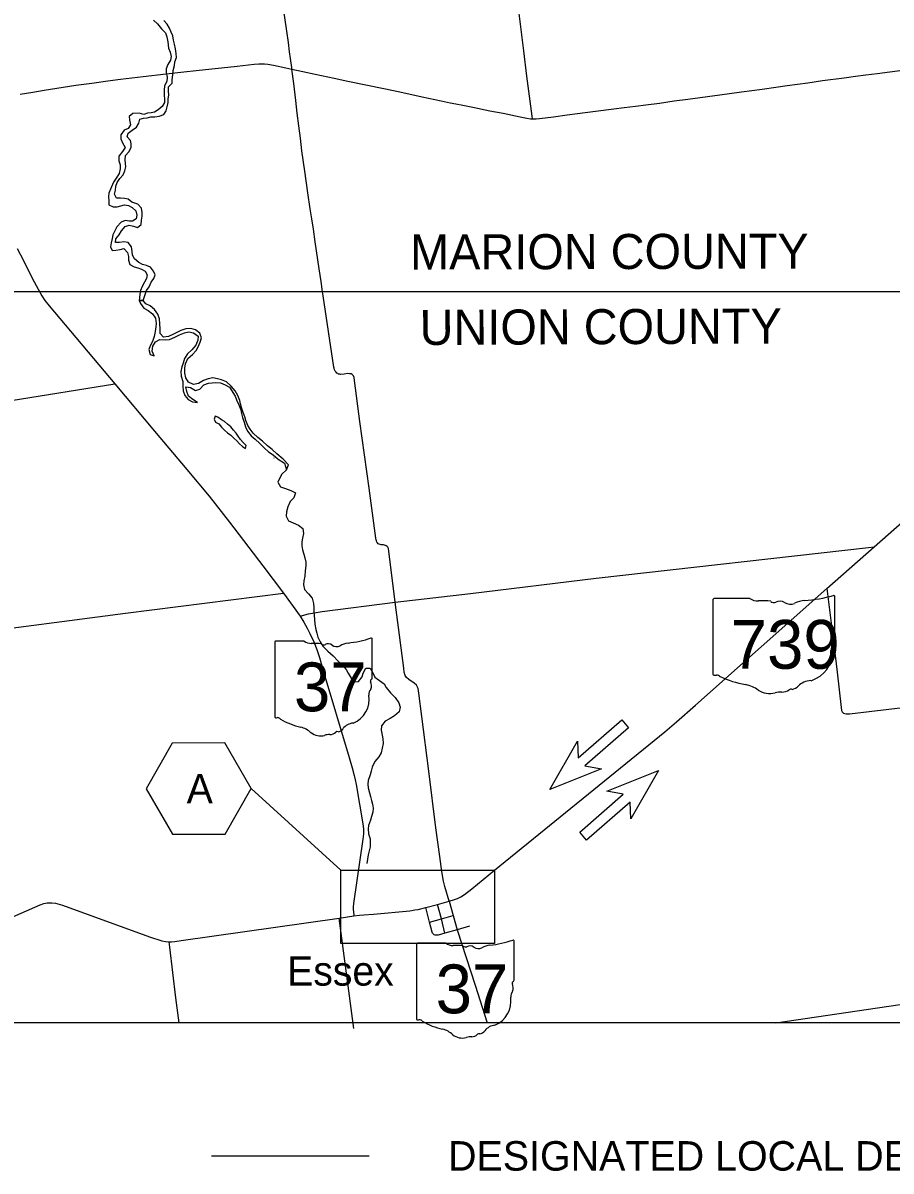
# Model space of a CAD drawing. Extents: x 0 to 680, y 0 to 440.
# Drawn here: x 170.3 to 252.8, y 124.6 to 233.7 of the extents above; entities that cross this region are included whole.
import ezdxf

# ---------------------------------------------------------------- set-up
doc = ezdxf.new("R2010")
doc.units = 0
for name, color, linetype in [('DV_X_County_Line', 7, 'Continuous'), ('GM_X_County_Road', 7, 'Continuous'), ('GM_X_County_Text', 7, 'Continuous'), ('GM_X_Minor_Lake', 7, 'Continuous'), ('GM_X_Minor_River', 7, 'Continuous'), ('GM_X_State_Location', 7, 'Continuous'), ('GM_X_State_Route', 7, 'Continuous'), ('GM_X_State_Shield', 7, 'Continuous'), ('GM_X_Township_Road', 7, 'Continuous'), ('GM_X_Unincorporated_Text', 7, 'Continuous'), ('MT_P_Text', 7, 'Continuous'), ('PM_P_Cells', 7, 'Continuous'), ('SH_Border', 7, 'Continuous'), ('SH_Text', 7, 'Continuous')]:
    doc.layers.add(name, color=color, linetype=linetype)

msp = doc.modelspace()

# ---------------------------------------------------------------- linework, layer by layer
at = {"layer": 'DV_X_County_Line'}
msp.add_line((399.36, 208.16), (30, 208.16), dxfattribs=at)
at = {"layer": 'GM_X_County_Road'}
for points in [[(218.73, 224.62), (218.7, 224.88), (218.22, 228.68), (217.91, 231.07), (217.41, 235.14), (217.28, 236.17), (216.98, 238.6), (216.66, 241.2), (216.47, 242.75), (216.3, 244.05), (216.15, 245.11), (215.96, 246.55), (215.7, 248.65), (215.5, 250.29), (215.19, 252.71), (214.96, 254.56), (214.7, 256.54), (214.45, 258.52)], [(170.05, 226.96), (171.24, 227.16), (172.32, 227.33), (175.35, 227.8), (176.86, 228.01), (178.38, 228.23), (179.57, 228.39), (181.74, 228.65), (183.92, 228.89), (185.33, 229.04), (187.07, 229.23), (188.59, 229.39), (190.66, 229.62), (192.29, 229.81), (192.72, 229.84), (193.05, 229.85), (193.27, 229.84), (193.59, 229.8), (194.13, 229.7), (195.3, 229.45), (195.88, 229.33)], [(195.88, 229.33), (196.91, 229.11), (198.08, 228.86), (199.9, 228.47), (201.19, 228.2), (204.6, 227.49), (206.14, 227.17), (208.25, 226.72), (210.07, 226.34), (210.93, 226.15), (211.46, 226.04), (212.11, 225.91), (213.07, 225.72), (214.68, 225.39), (215.97, 225.14), (217.57, 224.8), (218.22, 224.68), (218.55, 224.63), (218.73, 224.62)], [(218.73, 224.62), (218.87, 224.61), (219.1, 224.62), (219.42, 224.65), (220.73, 224.82), (222.03, 224.99), (223.01, 225.11), (224.74, 225.33), (226.48, 225.55), (227.45, 225.68), (228, 225.76), (228.54, 225.83), (229.51, 225.96), (230.81, 226.12), (232.22, 226.32), (233.52, 226.5), (236.56, 226.91), (238.62, 227.19), (240.57, 227.45), (241.87, 227.63), (242.95, 227.78), (244.9, 228.05), (246.31, 228.25), (248.37, 228.52), (249.46, 228.66), (250.43, 228.79), (251.52, 228.93), (252.71, 229.08), (253.9, 229.24)], [(205.69, 178.68), (205.09, 183.54), (205.06, 183.77), (205, 183.9), (204.93, 183.97), (204.83, 184.04), (204.76, 184.08), (204.69, 184.11), (204.58, 184.12), (204.44, 184.13), (204.35, 184.13), (204.25, 184.15), (204.18, 184.18), (204.09, 184.23), (204.01, 184.31), (203.95, 184.4), (203.91, 184.51), (203.88, 184.62), (203.85, 184.75), (203.22, 189.52), (202.34, 195.86), (201.83, 199.76), (201.79, 200.02), (201.73, 200.18), (201.66, 200.26), (201.59, 200.33), (201.51, 200.37), (201.43, 200.39), (201.36, 200.39), (201.2, 200.4), (200.84, 200.36), (200.53, 200.33), (200.42, 200.35), (200.31, 200.36), (200.23, 200.41), (200.15, 200.45), (200.07, 200.53), (199.98, 200.65), (199.93, 200.77), (199.89, 200.93), (199.87, 201.02), (198.85, 207.81)], [(151.97, 195.13), (169.18, 197.84), (179.06, 199.43)], [(151.97, 195.13), (153.03, 185.67), (154.24, 174.93), (154.31, 174.64), (154.43, 174.44), (154.6, 174.34), (154.82, 174.31), (155.07, 174.32), (164.52, 175.6), (180.06, 177.63), (195.08, 179.54)], [(196.67, 177.35), (197.44, 177.58), (198.74, 177.8), (205.69, 178.68), (212.86, 179.52), (224.8, 180.97), (250.68, 183.87), (251.21, 183.93)], [(246.72, 179.99), (247.37, 174.65), (247.71, 172.04), (248.09, 168.68), (248.13, 168.39), (248.18, 168.25), (248.32, 168.12), (248.56, 168.06), (248.87, 168.06), (270.78, 170.66), (313.8, 175.57), (322.56, 176.52), (329.32, 177.23), (332.35, 177.54), (334.92, 177.78)], [(210.82, 150.26), (210.42, 151.67), (210.29, 152.17), (210.13, 153.08), (209.93, 154.51), (209.57, 157.25), (208.88, 162.63), (208.22, 167.83), (207.95, 170.02), (207.88, 170.48), (207.71, 170.81), (207.5, 171), (207, 171.33), (206.78, 171.51), (206.65, 171.72), (206.56, 172.02), (206.53, 172.4), (205.69, 178.68)], [(241.88, 138.72), (262.29, 141.71), (275.58, 143.63), (287.35, 145.22), (316.8, 149.19)], [(185.15, 138.72), (184.85, 141.07), (184.26, 145.91), (184.2, 146.41)]]:
    msp.add_lwpolyline(points, dxfattribs=at)
at = {"layer": 'GM_X_Minor_Lake'}
for points in [[(188.57, 196.36), (188.49, 196.06), (188.63, 195.78), (188.94, 195.62), (189.2, 195.31), (189.46, 195.02), (189.77, 194.78), (190.06, 194.55), (190.36, 194.27), (190.63, 194.02), (190.89, 193.73), (191.17, 193.46), (191.47, 193.29), (191.5, 193.43)], [(191.5, 193.43), (191.53, 193.56), (191.24, 193.86), (190.99, 194.15), (190.77, 194.46), (190.58, 194.75), (190.34, 195.03), (190.08, 195.33), (189.75, 195.6), (189.46, 195.84), (189.17, 196.02), (188.85, 196.25), (188.57, 196.36)]]:
    msp.add_lwpolyline(points, dxfattribs=at)
at = {"layer": 'GM_X_Minor_River'}
msp.add_line((181.75, 207.36), (181.36, 207.36), dxfattribs=at)
for points in [[(182.72, 233.98), (183.1, 233.63), (183.48, 233.16), (183.85, 232.79), (183.98, 232.41), (184.08, 231.94), (184.15, 231.33), (184.3, 230.96), (184.4, 230.55), (184.33, 230.19), (184.08, 229.78), (183.91, 229.37), (183.93, 229.01), (184.03, 228.59), (183.99, 228.15), (183.77, 227.74), (183.75, 227.34), (183.74, 226.86), (183.76, 226.5), (183.77, 226.16), (183.53, 225.78), (183.18, 225.46), (182.83, 225.26), (182.49, 225.17), (182.16, 225.15), (181.81, 225.03), (181.37, 225.15), (180.76, 225.13), (180.42, 224.84), (180.44, 224.51), (180.53, 224.06), (180.32, 223.69), (179.94, 223.53), (179.63, 223.08), (179.61, 222.72), (179.78, 222.35), (180.04, 221.88), (179.79, 221.52), (179.42, 221.06), (179.43, 220.62), (179.54, 220.23), (179.55, 219.87), (179.46, 219.43), (179.16, 218.98), (178.93, 218.61), (178.64, 217.94), (178.47, 217.56), (178.44, 217.22), (178.49, 216.8), (178.49, 216.44), (178.9, 216.26), (179.26, 216.25), (179.63, 216.34), (179.96, 216.44), (180.35, 216.38), (180.69, 216.19), (181.05, 215.88), (181.13, 215.45), (181.07, 215.1), (180.74, 214.89), (180.4, 214.89), (180.02, 214.95), (179.65, 214.79), (179.25, 214.36), (179.03, 213.92), (178.87, 213.58), (178.79, 213.23), (178.71, 212.82), (178.64, 212.46)], [(182.51, 209.08), (182.76, 209.44), (182.88, 209.79), (182.73, 210.13), (182.45, 210.51), (182.07, 210.68), (181.67, 210.78), (181.33, 210.97), (180.93, 211.32), (180.74, 211.66), (180.69, 212.02), (180.63, 212.46), (180.32, 212.86), (179.9, 212.92), (179.5, 212.87), (179.11, 212.86), (179.13, 213.22), (179.45, 213.58), (179.68, 213.98), (180.03, 214.38), (180.42, 214.5), (180.82, 214.41), (181.19, 214.29), (181.55, 214.56), (181.58, 214.97), (181.65, 215.35), (181.64, 215.72), (181.57, 216.14), (181.23, 216.52), (180.67, 216.7), (180.3, 216.99), (179.96, 217.03), (179.6, 217.09), (179.2, 217.07), (179, 217.45), (179.12, 217.85), (179.15, 218.22), (179.26, 218.57), (179.51, 218.94), (179.83, 219.29), (179.99, 219.68), (180.09, 220.04), (180.07, 220.37), (180.02, 220.71), (180.05, 221.13), (180.38, 221.49), (180.6, 221.88), (180.6, 222.23), (180.54, 222.57), (180.23, 222.91), (180.3, 223.25), (180.69, 223.55), (181.11, 223.81), (181.34, 224.21), (181.42, 224.57), (181.77, 224.67), (182.11, 224.72), (182.48, 224.79), (182.84, 224.8), (183.25, 224.87), (183.69, 225.03), (183.91, 225.38), (184.01, 225.76), (184.1, 226.17), (184.11, 226.5), (184.17, 226.9), (184.14, 227.24), (184.16, 227.65), (184.48, 227.99), (184.48, 228.33), (184.57, 228.81), (184.6, 229.21), (184.71, 229.69), (184.75, 230.03), (184.9, 230.43), (184.88, 230.81), (184.81, 231.26), (184.71, 231.72), (184.61, 232.08), (184.55, 232.5), (184.4, 232.85), (184.23, 233.22), (184.01, 233.61), (183.69, 233.95)], [(178.64, 212.46), (178.8, 212.11), (179.13, 212.14), (179.54, 212.2), (179.91, 212.28), (180.26, 211.91), (180.33, 211.53), (180.35, 211.17), (180.47, 210.78), (180.88, 210.56), (181.24, 210.46), (181.58, 210.34), (181.93, 210.14), (182.13, 209.79), (182.07, 209.43), (181.86, 209.08), (181.64, 208.69), (181.5, 208.29), (181.42, 207.95), (181.38, 207.59), (181.36, 207.36)], [(181.75, 207.36), (182.07, 208.31), (182.32, 208.65), (182.51, 209.08)], [(181.36, 207.36), (181.75, 207.36)], [(181.36, 207.36), (181.48, 207.07), (181.81, 206.62), (182.23, 206.41), (182.64, 206.09), (182.9, 205.68), (182.96, 205.17), (182.93, 204.84), (182.89, 204.41), (182.8, 203.93), (182.64, 203.46), (182.39, 203.04), (182.27, 202.69), (182.41, 202.21), (182.77, 202.08), (182.6, 202.55), (182.65, 203.01), (182.91, 203.43), (183.33, 203.64), (183.84, 203.61), (184.24, 203.63), (184.75, 203.87), (185.2, 204.09), (185.67, 204.29), (186.09, 204.37), (186.53, 204.28), (186.96, 203.96), (186.94, 203.59), (186.75, 203.12), (186.37, 202.66), (185.96, 202.28), (185.68, 201.84), (185.55, 201.4), (185.43, 201.04), (185.33, 200.6), (185.35, 200.16), (185.51, 199.66), (185.5, 199.22), (185.54, 198.78), (185.71, 198.32), (186.02, 197.93), (186.43, 197.72), (186.89, 197.67), (186.46, 197.94), (186.05, 198.25), (185.9, 198.71), (185.81, 199.14), (186.24, 199.07), (186.71, 198.81), (187.12, 198.91), (187.52, 199.35), (187.96, 199.5), (188.31, 199.53), (188.64, 199.56), (189.1, 199.52), (189.52, 199.35), (189.94, 199.11), (190.49, 198.25), (190.62, 197.91), (190.82, 197.44), (191.01, 196.96), (191.08, 196.6), (191.19, 196.22), (191.34, 195.78), (191.47, 195.36), (191.65, 194.93), (191.99, 194.5), (192.4, 194.16), (192.83, 193.75), (193.24, 193.35), (193.66, 192.98), (194.08, 192.68), (194.56, 192.28)], [(195.05, 192.27), (194.43, 192.78), (194.01, 193.2), (193.55, 193.54), (193.08, 193.98), (192.65, 194.34), (192.18, 194.73), (191.91, 195.13), (191.68, 195.47), (191.5, 195.94), (191.4, 196.29), (191.23, 196.7), (191.09, 197.17), (191, 197.52), (190.94, 197.86), (190.75, 198.32), (190.49, 198.76), (190.11, 199.2), (189.67, 199.63), (189.18, 199.81), (188.82, 199.9), (188.37, 200.01), (187.91, 199.92), (187.46, 199.74), (187, 199.47), (186.52, 199.37), (186.05, 199.58), (185.78, 199.99), (185.69, 200.44), (185.7, 200.93), (185.75, 201.34), (185.97, 201.84), (186.42, 202.21), (186.78, 202.6), (186.96, 202.95), (187.16, 203.39), (187.28, 203.81), (187.11, 204.24), (186.71, 204.55), (186.27, 204.68), (185.8, 204.66), (185.32, 204.5), (184.94, 204.31), (184.61, 204.14), (184.15, 203.94), (183.68, 203.88), (183.35, 204.23), (183.35, 204.66), (183.32, 205.14), (183.29, 205.62), (183.12, 206.06), (182.82, 206.51), (182.4, 206.83), (181.98, 207.02), (181.75, 207.36)], [(194.19, 192.38), (194.18, 192.39)], [(194.56, 192.28), (195.17, 191.88), (195.36, 191.26)], [(195.36, 191.26), (195.55, 191.72), (195.05, 192.27)], [(195.36, 191.26), (194.89, 190.81), (194.54, 190.09), (194.78, 189.65), (195.28, 189.47), (195.77, 189.28), (196.23, 189.07), (196.05, 188.6), (195.71, 188.26), (195.5, 187.75), (195.36, 187.28), (195.33, 186.84), (195.54, 186.41), (196, 186.21), (196.5, 186.01), (196.93, 185.67), (196.98, 185.22), (196.87, 184.77), (196.82, 184.42), (196.83, 184.03), (196.89, 183.67), (197, 183.24), (197.09, 182.91), (197.2, 182.49), (197.21, 182.13), (197.15, 181.65), (197.1, 181.16), (197.01, 180.71), (196.97, 180.33), (197.08, 179.9), (197.46, 179.48), (197.81, 179.06), (197.93, 178.57), (197.95, 178.13), (197.95, 177.78), (197.99, 177.43), (198.01, 177.08), (198.07, 176.58), (198.14, 176.08), (198.24, 175.75), (198.34, 175.36), (198.55, 174.9), (198.82, 174.5), (199.3, 174.02), (199.79, 173.59), (200.28, 173.08), (200.64, 172.72), (201.02, 172.28), (201.21, 171.92), (201.5, 171.45), (201.87, 171.1), (202.22, 171.15), (202.55, 171.59), (202.65, 171.94), (202.89, 172.42), (203.33, 172.42), (203.58, 171.97), (203.75, 171.56), (204.21, 171.25), (204.64, 170.91), (204.84, 170.58), (205.25, 170.08), (205.69, 169.62), (206.05, 169.13), (206.18, 168.71), (206.06, 168.25), (205.63, 167.87), (205.21, 167.63), (204.74, 167.36), (204.38, 166.94), (204.35, 166.52), (204.44, 166.03), (204.52, 165.69), (204.54, 165.25), (204.46, 164.8), (204.37, 164.37), (204.14, 163.99), (203.76, 163.53), (203.51, 163), (203.42, 162.63), (203.32, 162.27), (203.14, 161.72), (203.1, 161.39), (203.14, 161.05), (203.26, 160.56), (203.34, 160.22), (203.45, 159.82), (203.55, 159.47), (203.6, 159.1), (203.56, 158.74), (203.45, 158.3), (203.34, 157.97), (203.16, 157.47), (203.11, 157.14), (203.16, 156.67), (203.31, 156.19), (203.33, 155.78), (203.3, 155.43), (203.22, 155.06), (203.14, 154.67), (203, 153.84)]]:
    msp.add_lwpolyline(points, dxfattribs=at)
at = {"layer": 'GM_X_State_Route'}
for p, q in [((192.01, 160.98), (200.54, 153.21)), ((208.61, 149.65), (209.72, 149.95)), ((209.72, 149.95), (210.82, 150.26))]:
    msp.add_line(p, q, dxfattribs=at)
for points in [[(169.75, 212.3), (170.35, 211.14), (171.19, 209.48), (171.75, 208.42), (172.11, 207.78)], [(172.11, 207.78), (172.38, 207.36), (172.8, 206.84), (179.06, 199.43), (182.82, 194.92), (185.89, 191.28), (188.02, 188.74), (189.93, 186.3), (193.12, 182.13), (195.08, 179.54), (196.67, 177.35), (197.01, 176.79), (197.34, 176.2), (197.59, 175.71), (197.96, 174.91), (198.24, 174.19), (198.49, 173.41), (198.83, 172.27), (201.32, 163.92), (201.6, 162.95), (201.79, 162.22), (201.88, 161.81), (201.98, 161.37), (202.62, 157.61), (202.68, 157.13), (202.68, 156.66), (202.63, 156.17), (201.74, 150.03), (201.71, 149.72), (201.71, 149.44), (201.73, 149.29), (201.77, 148.87)], [(215.14, 153.21), (231.31, 166.36), (232.44, 167.31), (234.23, 168.9), (246.72, 179.99), (251.21, 183.93), (258.65, 190.5), (266.46, 196.93), (267.15, 197.47), (267.72, 197.83), (268.06, 198.04), (268.44, 198.23), (268.93, 198.45), (292.62, 208.16)], [(210.82, 150.26), (211.33, 150.42), (211.62, 150.53), (211.94, 150.69), (212.29, 150.91), (212.97, 151.44), (215.14, 153.21)], [(152.34, 141.32), (171.94, 149.92), (172.29, 150.03), (172.63, 150.1), (173.05, 150.11), (173.41, 150.07), (174.06, 149.89), (182.35, 146.88), (183.51, 146.5), (183.87, 146.43), (184.2, 146.41), (184.42, 146.41), (184.75, 146.44), (185.34, 146.52), (200.38, 148.65), (201.77, 148.87)], [(207.56, 149.43), (207.87, 149.48), (208.61, 149.65)], [(210.82, 150.26), (211.2, 148.91), (211.6, 147.55), (213.28, 142.27), (214.45, 138.72)], [(201.77, 148.87), (202.3, 148.94), (202.7, 148.97), (203.62, 149.04), (207.1, 149.35), (207.56, 149.43)]]:
    msp.add_lwpolyline(points, dxfattribs=at)
msp.add_lwpolyline([(189.5, 165.3), (184.5, 165.28), (182.01, 160.95), (184.52, 156.62), (189.52, 156.64), (192.01, 160.98)], close=True, dxfattribs=at)
at = {"layer": 'GM_X_State_Shield'}
for p, q in [((239.4, 179.02), (236, 179.02)), ((247.49, 175.51), (247.49, 179.19)), ((235.89, 178.9), (235.89, 171.85)), ((194.24, 174.86), (194.24, 167.82)), ((197.05, 174.98), (194.33, 174.98)), ((203.52, 171.47), (203.52, 175.16)), ((247.49, 175.51), (247.49, 175.51)), ((203.52, 171.47), (203.52, 171.47)), ((210.52, 146.28), (207.81, 146.28)), ((217, 142.76), (217, 146.45)), ((207.71, 146.15), (207.71, 139.11)), ((216.99, 142.77), (217, 142.76))]:
    msp.add_line(p, q, dxfattribs=at)
for centre, radius, start, end in [((194.35, 174.88), 0.108, 98.1301, 188.1301), ((197.7, 175.8), 1.04, 231.6195, 271.1119), ((198.04, 171.03), 3.74, 80.4867, 94.9883), ((198.89, 174.91), 0.301, 219.7921, 297.1024), ((199.33, 174.1), 0.626, 54.4667, 119.1411), ((200.14, 175.21), 0.753, 233.8562, 294.8282), ((201.47, 172.83), 1.98, 97.3462, 120.7689), ((200.21, 184.59), 9.84, 275.8445, 288.9065), ((203.42, 175.17), 0.103, 351.8621, 97.738), ((203.5, 171.2), 0.16, 107.944, 210.337), ((203.41, 171.46), 0.111, 289.6038, 7.7341), ((203.89, 169.93), 0.698, 136.8065, 186.9296), ((202.48, 170.74), 0.96, 340.033, 23.6496), ((200.77, 169.46), 2.46, 292.3089, 8.9858), ((194.35, 167.8), 0.108, 171.9584, 258.3066), ((194.36, 168.52), 0.828, 267.339, 280.6039), ((194.53, 167.41), 0.298, 29.7484, 93.2717), ((198.3, 173.74), 7.11, 240.4129, 257.1985), ((201.8, 165.84), 1.35, 94.4031, 142.5768), ((196.18, 164.65), 2.22, 47.1842, 75.836), ((198.59, 167.38), 1.41, 230.7004, 286.2918), ((199.4, 164.94), 1.16, 85.6951, 111.2099), ((199.51, 166.85), 0.752, 268.777, 315.5493), ((200.19, 166.17), 0.212, 65.7517, 132.6484), ((200.1, 167.13), 0.795, 282.8732, 323.2771), ((207.82, 146.17), 0.108, 98.1301, 188.1301), ((211.17, 147.09), 1.04, 231.6195, 271.1119), ((213.69, 155.88), 9.84, 275.8445, 288.9065), ((216.89, 146.47), 0.103, 351.8621, 97.738), ((211.52, 142.32), 3.74, 80.4867, 94.9883), ((212.37, 146.21), 0.301, 219.7921, 297.1024), ((212.81, 145.39), 0.626, 54.4667, 119.1411), ((213.62, 146.51), 0.753, 233.8562, 294.8282), ((214.94, 144.12), 1.98, 97.3462, 120.7689), ((216.97, 142.49), 0.16, 107.944, 210.337), ((215.95, 142.03), 0.96, 340.033, 23.6496), ((216.89, 142.75), 0.111, 289.6038, 7.7341), ((214.24, 140.75), 2.46, 292.3089, 8.9858), ((217.37, 141.22), 0.698, 136.8065, 186.9296), ((207.82, 139.09), 0.108, 171.9584, 258.3066), ((207.84, 139.82), 0.828, 267.339, 280.6039), ((208.01, 138.7), 0.298, 29.7484, 93.2717), ((211.78, 145.03), 7.11, 240.4129, 257.1985), ((209.66, 135.95), 2.22, 47.1842, 75.836), ((212.06, 138.67), 1.41, 230.7004, 286.2918), ((212.98, 138.14), 0.752, 268.777, 315.5493), ((213.66, 137.46), 0.212, 65.7517, 132.6484), ((213.57, 138.43), 0.795, 282.8732, 323.2771), ((215.28, 137.13), 1.35, 94.4031, 142.5768), ((212.88, 136.23), 1.16, 85.6951, 111.2099)]:
    msp.add_arc(centre, radius, start, end, dxfattribs=at)
for centre, major_axis, start_param, end_param in [((236.02, 178.91), (0.134, 0), 1.712693, 3.28349), ((240.21, 179.84), (1.3, 0), 4.042523, 4.731795), ((243.36, 188.62), (12.3, 0), 4.814394, 5.042369), ((247.36, 179.21), (0.129, 0), 6.141152, 7.989035), ((240.64, 175.07), (4.68, 0), 1.404758, 1.657858), ((241.7, 178.95), (0.376, 0), 3.836095, 5.185415), ((242.25, 178.14), (0.782, 0), 0.950623, 2.079405), ((243.26, 179.25), (0.941, 0), 4.081561, 5.145723), ((244.93, 176.87), (2.48, 0), 1.699011, 2.107814), ((247.46, 175.24), (0.2, 0), 1.883978, 3.671073), ((246.19, 174.77), (1.2, 0), 5.934695, 6.695948), ((247.35, 175.5), (0.138, 0), 5.05454, 6.418171), ((244.05, 173.5), (3.08, 0), 5.101752, 6.440018), ((247.95, 173.97), (0.873, 0), 2.387724, 3.262537), ((236.02, 171.84), (0.136, 0), 3.00124, 4.508301), ((236.04, 172.56), (1.03, 0), 4.665946, 4.897461), ((236.25, 171.45), (0.373, 0), 0.519207, 1.627899), ((240.96, 177.78), (8.88, 0), 4.195997, 4.488961), ((238.32, 168.69), (2.78, 0), 0.823519, 1.323587), ((241.32, 171.41), (1.76, 0), 4.026481, 4.996735), ((242.47, 170.89), (0.94, 0), 4.691044, 5.507374), ((243.32, 170.2), (0.265, 0), 1.147584, 2.315152), ((243.21, 171.17), (0.994, 0), 4.937069, 5.64225), ((245.34, 169.88), (1.69, 0), 1.647645, 2.488434), ((242.34, 168.98), (1.45, 0), 1.495662, 1.94098)]:
    msp.add_ellipse(centre, major_axis=major_axis, ratio=0.8, start_param=start_param, end_param=end_param, dxfattribs=at)
at = {"layer": 'GM_X_Township_Road'}
for p, q in [((201.76, 138.18), (200.38, 148.65)), ((212.76, 147.88), (211.6, 147.55))]:
    msp.add_line(p, q, dxfattribs=at)
for points in [[(195.88, 229.33), (195.86, 229.48), (195.75, 230.34), (195.65, 230.99), (195.54, 231.86), (195.38, 232.94), (195.19, 234.24), (194.86, 236.51), (194.77, 237.14), (194.65, 238.01), (194.53, 238.88), (194.3, 240.41), (193.97, 242.79), (193.74, 244.52), (193.57, 245.71), (193.3, 247.66), (193.06, 249.4), (192.83, 251.02), (192.48, 253.62), (192.17, 255.9), (192.07, 256.61)], [(198.85, 207.81), (198.79, 208.16), (198.65, 209.17), (198.47, 210.35), (198.21, 212.08), (198.09, 212.94), (197.92, 214.13), (197.77, 215.1), (197.62, 216.07), (197.4, 217.59), (197.1, 219.64), (196.83, 221.58), (196.68, 222.77), (196.53, 223.96), (196.39, 225.16), (196.25, 226.35), (196.05, 227.97), (195.88, 229.33)], [(211.6, 147.55), (210.42, 147.23), (209.77, 147.05), (209.59, 147.02), (209.48, 147.04), (209.4, 147.07), (209.33, 147.12), (209.25, 147.22), (209.21, 147.33), (208.97, 148.27), (208.61, 149.65)], [(210.42, 147.23), (210.1, 148.59), (209.72, 149.95)], [(208.97, 148.27), (210.1, 148.59), (211.2, 148.91)]]:
    msp.add_lwpolyline(points, dxfattribs=at)
at = {"layer": 'MT_P_Text'}
msp.add_line((188.22, 126.06), (203.22, 126.06), dxfattribs=at)
at = {"layer": 'PM_P_Cells'}
for p, q in [((223.07, 163.88), (227.22, 167.5)), ((227.22, 167.5), (227.88, 166.74)), ((227.55, 167.12), (227.55, 167.12)), ((227.88, 166.74), (223.73, 163.13)), ((220.39, 160.87), (223.01, 165.47)), ((223.01, 165.47), (223.07, 163.88)), ((225.3, 162.85), (220.39, 160.87)), ((223.73, 163.13), (225.3, 162.85)), ((225.81, 160.72), (230.71, 162.7)), ((230.71, 162.7), (228.09, 158.1)), ((230.71, 162.7), (230.71, 162.7)), ((220.39, 160.87), (220.39, 160.87)), ((223.23, 156.83), (227.37, 160.44)), ((227.37, 160.44), (225.81, 160.72)), ((228.03, 159.69), (223.89, 156.07)), ((228.09, 158.1), (228.03, 159.69)), ((223.89, 156.07), (223.23, 156.83)), ((223.56, 156.45), (223.56, 156.45))]:
    msp.add_line(p, q, dxfattribs=at)
at = {"layer": 'SH_Border'}
msp.add_lwpolyline([(200.54, 153.21), (215.14, 153.21), (215.14, 146.25), (200.54, 146.25)], close=True, dxfattribs=at)
at = {"layer": 'SH_Text'}
msp.add_lwpolyline([(30, 430), (466.92, 430), (466.92, 291.27), (342.9, 138.72), (30, 138.72)], close=True, dxfattribs=at)

# ---------------------------------------------------------------- texts
at = {"layer": 'GM_X_County_Text'}
for s, rotation, p in [('MARION COUNTY', 0.1378, (207.11, 210.29)), ('UNION COUNTY', 0.2432, (208.02, 203.12))]:
    msp.add_text(s, height=3.3333, rotation=rotation, dxfattribs=at).set_placement(p)
at = {"layer": 'GM_X_State_Location'}
for s, p in [('s', (241.56, 174.91)), ('r', (241.56, 174.91)), ('s', (202.52, 156.66)), ('r', (202.51, 156.66))]:
    msp.add_text(s, height=0.00667, dxfattribs=at).set_placement(p)
for s, p in [('739', (239.2, 174.42)), ('37', (200.84, 156.18))]:
    msp.add_text(s, height=0.00667, rotation=0, dxfattribs=at).set_placement(p)
at = {"layer": 'GM_X_State_Route'}
msp.add_text('A', height=2.8, dxfattribs=at).set_placement((185.87, 159.56))
at = {"layer": 'GM_X_State_Shield'}
for s, p in [('739', (237.59, 172.35)), ('37', (196.07, 168.31)), ('37', (209.54, 139.61))]:
    msp.add_text(s, height=4.641, dxfattribs=at).set_placement(p)
at = {"layer": 'GM_X_Unincorporated_Text'}
msp.add_text('Essex', height=2.78, rotation=0, dxfattribs=at).set_placement((195.43, 142.24))
at = {"layer": 'SH_Text'}
msp.add_text('DESIGNATED LOCAL DETOUR ROUTE', height=2.8, dxfattribs=at).set_placement((210.72, 124.66))

doc.saveas('drawing.dxf')
